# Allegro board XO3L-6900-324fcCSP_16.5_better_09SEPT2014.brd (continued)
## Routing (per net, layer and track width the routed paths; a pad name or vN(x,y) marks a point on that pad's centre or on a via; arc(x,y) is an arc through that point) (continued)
PT22A: length 4.6
  TOP w0.102: BGA.A10 v1(13.14,17.14)
  L3_SIGNAL1 w0.102: v1(13.14,17.14) 12.94,17.33 12.94,21.39
PT22B: length 6.2
  TOP w0.102: BGA.D9 v1(12.26,15.64)
  L3_SIGNAL1 w0.102: 12.75,21.39 12.75,16.13 v1(12.26,15.64)
PT22C: length 4.5
  TOP w0.102: BGA.A9 v1(12.26,17.14)
  L3_SIGNAL1 w0.102: 12.26,21.39 12.26,17.14 v1(12.26,17.14)
PT22D: length 5.1
  TOP w0.102: BGA.B9 v1(12.26,16.64)
  L3_SIGNAL1 w0.102: v1(12.26,16.64) 12.51,16.89 12.51,17.24 12.45,17.3 12.45,21.39
PT25A: length 5.7
  TOP w0.102: BGA.C9 v1(12.26,16.14)
  L4_SIGNAL2 w0.102: v1(12.26,16.14) 12.26,16.28 12.01,16.53 12.01,17.42 12.17,17.57 12.17,21.39
PT25B: length 6.7
  TOP w0.102: BGA.E9 v1(12.26,15.14)
  L4_SIGNAL2 w0.102: v1(12.26,15.14) 12.51,15.39 12.51,17.45 12.36,17.6 12.36,21.39
PT25C: length 5.1
  TOP w0.102: BGA.B8 v1(11.76,16.64)
  L3_SIGNAL1 w0.102: 12.01,21.39 12.01,16.89 v1(11.76,16.64)
PT25D: length 4.5
  TOP w0.102: BGA.A8 v1(11.76,17.14)
  L3_SIGNAL1 w0.102: v1(11.76,17.14) 11.76,17.47 11.83,17.53 11.83,21.39
PT26A: length 6.2
  TOP w0.102: BGA.D8 v1(11.76,15.64)
  BOTTOM w0.102: v1(11.76,15.64) 12.01,15.89 12.01,17.32 11.86,17.48 11.86,21.45
PT26B: length 7.2
  TOP w0.102: BGA.F8 v1(11.76,14.64)
  BOTTOM w0.102: v1(11.76,14.64) 11.51,14.89 11.51,17.31 11.67,17.47 11.67,21.45
PT26C: length 5.7
  TOP w0.102: BGA.C8 v1(11.76,16.14)
  L4_SIGNAL2 w0.102: 11.36,21.39 11.36,17.54 11.51,17.39 11.51,16.51 11.76,16.26 v1(11.76,16.14)
PT26D: length 7
  TOP w0.102: BGA.E8 v1(11.76,15.14)
  L4_SIGNAL2 w0.102: v1(11.76,15.14) 11.51,15.39 11.51,16.14 11.51,16.14 11.51,16.24 11.36,16.39 11.16,16.39 11.06,16.49 11.01,16.53 11.01,17.42 11.17,17.57 11.17,21.39
PT27A: length 7.2
  TOP w0.102: BGA.C7 v1(11.26,16.14)
  L4_SIGNAL2 w0.102: v1(11.26,16.14) 11.12,16.14 10.87,16.39 9.66,16.39 9.51,16.53 9.51,16.74 9.08,17.18 9.08,21.39
PT27B: length 5.2
  TOP w0.102: BGA.B3 v1(9.26,16.64)
  L4_SIGNAL2 w0.102: 8.89,21.39 8.89,17.01 9.14,16.76 v1(9.26,16.64)
PT27C: length 4.5
  TOP w0.102: BGA.A7 v1(11.26,17.14)
  L3_SIGNAL1 w0.102: v1(11.26,17.14) 11.26,17.43 11.33,17.5 11.33,21.39
PT27D: length 5.1
  TOP w0.102: BGA.B7 v1(11.26,16.64)
  L3_SIGNAL1 w0.102: 11.51,21.39 11.51,16.89 v1(11.26,16.64)
PT28A: length 4.5
  TOP w0.102: BGA.A6 v1(10.76,17.14)
  L3_SIGNAL1 w0.102: v1(10.76,17.14) 10.76,17.14 10.76,21.39
PT28B: length 6.6
  TOP w0.102: BGA.E7 v1(11.26,15.14)
  L3_SIGNAL1 w0.102: v1(11.26,15.14) 11.01,15.39 11.01,17.32 10.95,17.38 10.95,21.39
PT32A: length 6.6
  TOP w0.102: BGA.D7 v1(11.26,15.64)
  L6_SIG3 w0.102: 10.38,21.45 10.38,17.6 10.51,17.46 10.51,16.03 10.66,15.89 11.01,15.89 v1(11.26,15.64)
PT32B: length 7.2
  TOP w0.102: BGA.D6 v1(10.76,15.64)
  L6_SIG3 w0.102: 10.19,21.45 10.19,17.57 10.01,17.39 10.01,15.53 10.16,15.39 10.51,15.39 v1(10.76,15.64)
PT33A: length 7.8
  TOP w0.102: BGA.G8 v1(11.76,14.14)
  L6_SIG3 w0.102: 11.63,21.45 11.63,17.62 12.01,17.24 12.01,14.39 v1(11.76,14.14)
PT33B: length 5.9
  TOP w0.102: BGA.C6 v1(10.76,16.14)
  L6_SIG3 w0.102: v1(10.76,16.14) 11.01,16.39 11.01,17.24 11.44,17.67 11.44,21.45
PT33C: length 5.6
  TOP w0.102: BGA.B5 v1(10.26,16.64)
  L4_SIGNAL2 w0.102: v1(10.26,16.64) 10.15,16.64 9.89,16.89 9.66,16.89 9.51,17.03 9.51,17.42 9.67,17.57 9.67,21.39
PT33D: length 5.6
  TOP w0.102: BGA.B6 v1(10.76,16.64)
  L4_SIGNAL2 w0.102: v1(10.76,16.64) 10.51,16.89 10.16,16.89 10.01,17.04 10.01,17.39 9.86,17.54 9.86,21.39
PT34A: length 6.7
  TOP w0.102: BGA.A4 v1(9.76,17.14)
  BOTTOM w0.102: 3.58,16.5 8.19,16.5 8.83,17.14 v1(9.76,17.14)
PT34B: length 8.1
  TOP w0.102: BGA.E6 v1(10.76,15.14)
  BOTTOM w0.102: 3.58,16.31 8.18,16.31 8.61,15.89 10.37,15.89 10.51,15.74 10.51,15.39 v1(10.76,15.14)
PT34C: length 7.2
  TOP w0.102: BGA.F7 v1(11.26,14.64)
  BOTTOM w0.102: v1(11.26,14.64) 11.01,14.89 11.01,17.39 10.86,17.54 10.86,21.45
PT34D: length 4.7
  TOP w0.102: BGA.A5 v1(10.26,17.14)
  BOTTOM w0.102: v1(10.26,17.14) 10.67,17.54 10.67,21.45
PT35A: length 6.2
  TOP w0.102: BGA.D4 v1(9.76,15.64)
  L3_SIGNAL1 w0.102: 10.17,21.39 10.17,17.48 10.01,17.33 10.01,15.89 v1(9.76,15.64)
PT35B: length 5.7
  TOP w0.102: BGA.C5 v1(10.26,16.14)
  L3_SIGNAL1 w0.102: 10.36,21.39 10.36,17.45 10.51,17.29 10.51,16.39 v1(10.26,16.14)
PT35C: length 7.5
  TOP w0.102: BGA.D5 v1(10.26,15.64)
  L3_SIGNAL1 w0.102: v1(10.26,15.64) 10.01,15.39 9.7,15.39 9.7,15.39 9.66,15.39 9.51,15.54 9.51,15.76 9.39,15.89 8.48,15.89 8.11,16.26 3.58,16.26
PT35D: length 5.5
  TOP w0.102: BGA.B2 v1(8.76,16.64)
  L3_SIGNAL1 w0.102: 3.58,16.45 8.17,16.45 8.36,16.64 v1(8.76,16.64)
PT36A: length 4.5
  TOP w0.102: 9.3,21.39 9.3,17.45 9.45,17.3 BGA.A3
PT36B: length 4.5
  TOP w0.102: BGA.A2 8.95,17.3 9.11,17.46 9.11,21.39
PT36C: length 5.8
  TOP w0.102: BGA.C4 v1(9.76,16.14)
  L3_SIGNAL1 w0.102: v1(9.76,16.14) 9.76,16.28 9.51,16.54 9.51,16.74 9.38,16.87 9.14,17.11 9.14,21.39
PT36D: length 5.2
  TOP w0.102: BGA.B4 v1(9.76,16.64)
  L3_SIGNAL1 w0.102: v1(9.76,16.64) 9.76,16.75 9.7,16.82 9.57,16.95 9.33,17.19 9.33,21.39

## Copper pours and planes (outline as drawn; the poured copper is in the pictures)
GND on L2_GND: 3.58,21.45 11.45,21.45 11.45,13.32 13.95,13.32 13.95,21.45 21.82,21.45 21.82,4.02 3.58,4.02
VCC on L5_PWR: 11.51,11.58 11.08,11.58 11.08,21.45 14.39,21.45 14.39,11.58 13.95,11.58 13.95,12.04 11.51,12.04
VCCIO0 on L2_GND: 11.58,13.45 11.58,21.45 13.82,21.45 13.82,13.45
VCCIO1 on L5_PWR: 3.58,21.45 3.58,4.02 10.95,4.02 10.95,21.45
VCCIO2 on L5_PWR: 11.08,11.45 11.08,4.02 14.39,4.02 14.39,11.45 13.82,11.45 13.82,11.92 11.64,11.92 11.64,11.45
VCCIO3 on L5_PWR: 14.51,11.95 14.51,4.02 21.82,4.02 21.82,11.95
VCCIO4 on L5_PWR: 14.51,13.32 14.51,12.08 21.82,12.08 21.82,13.32
VCCIO5 on L5_PWR: 14.51,13.45 14.51,21.45 21.82,21.45 21.82,13.45

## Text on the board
User.Comments: ASP | XXXXXXXX | 09/03/14 | MM/DD/YY | DWG NO: | XO3L-69E-324FCCSP | REVISION | 1.0 | SHEET | 1 | OF | LATTICE SEMICONDUCTOR CORPORATION | XO3L-69E-324FCCSP PCB BREAKOUT
Ref Des/Silkscreen Top: A | B | C | D | E | F | G | H | J | K | L | M | N | P | R | T | U | V | 1 | 2 | 3 | 4 | 5 | 6 | 7 | 8 | 9 | 10 | 11 | 12 | 13 | 14 | 15 | 16 | 17 | 18 | PCB BREAKOUT | XO3L-69E-324fcCSP | SEMICONDUCTOR | LATTICE
PAGE_OUTLINE: SPECIAL INSTRUCTIONS: | LIKE VIA FILL | SPECIFY ANY SPECIAL INSTRUCTIONS | POWER   PLANE  (L7) | SECONDARY SIDE (L8) | SECONDARY SILKSCREEN | GND     PLANE  (L5) | SECONDARY SOLDERMASK | GND     PLANE  (L2) | PRIMARY SIDE   (L1) | PRIMARY SOLDERMASK | PRIMARY SILKSCREEN | SIGNAL 4       (L4) | SIGNAL 3       (L3) | SIGNAL 3       (L6) | DESIGNED BY: | APPROVED BY: | SIGNATURES         DATE | REV | 1 | INITIAL RELEASE | SPACE/NECK DOWN SPACE | ESCAPE VIA DRILL | TRACE WIDTH/NECK DWN | ESCAPE VIA PAD | LAND OPENING | PACKAGE SIZE | LAND PAD | PITCH | DESCRIPTION | 0.3048 | 0.50 | 0.2235 | 10 X 10 | 0.1016 | 0.127 | 0.08636 | MM | 09/14/2014 | DATE | 12 | 19.68 | 8.8 | 4.0 | 5.00 | 3.4 | MILS | APPEOVED | X. XXXXX | 8 LAYER STACKUP | PCB BREAKOUT DETAILS | REVISION
